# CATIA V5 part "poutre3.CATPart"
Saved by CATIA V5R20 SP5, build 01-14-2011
Part number: poutre3
Bounding box of the stored display mesh (mm): x 0 to 200, y 180.036 to 1475.177, z 210.526 to 649.964
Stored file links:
  F:\iao fini\poutre3.CATPart
  F:\iao fini\iao-finipbgliss.CATProduct
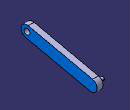
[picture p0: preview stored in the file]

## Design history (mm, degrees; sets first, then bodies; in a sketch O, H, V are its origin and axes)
External parameters (linked from other documents)
  External.rayontrou = 50 mm
  External.epaisseur = 50 mm
Set1
  Plane1 "Plan3": linked copy from another document
  Point1: linked copy from another document
  Point2 "Abis": linked copy from another document
  Point3: linked copy from another document
Body1 (main body)
  Sketch1 on Plane1, origin (100, 0, 0), H (0, 1, 0), V (0, 0, 1)
    circle A1 centre (280, 550) radius 50
    point P1 (280, 550)
    reference projected point E1 (280, 550) from Point2
    circle A2 centre (1375.213, 310.49) radius 25
    point P2 (1375.213, 310.49)
    reference projected point E2 (1375.213, 310.49) from Point3
    arc A3 centre (280, 550) radius 100 from (301.3639, 647.6913) to (258.6361, 452.3087) ccw
    point P3 (280, 550)
    reference projected point E3 (280, 550) from Point2
    arc A4 centre (1375.213, 310.49) radius 100 from (1353.8491, 212.7987) to (1396.5769, 408.1813) ccw
    line L1 (301.3639, 647.6913) -> (1396.5769, 408.1813)
    line L2 (258.6361, 452.3087) -> (1353.8491, 212.7987)
    radius A2 = 25 {= 1/2*External.rayontrou}
    radius A1 = 50 {= External.rayontrou}
    radius A3 = 100 {= External.rayontrou *2}
    radius A4 = 100 {= External.rayontrou *2}
    coincidence: P1 E1, E2 P2, E3 P3
    concentricity: A4 A2
    tangency: L1 A4, L2 A4, L2 A3
    parallelism: L2 L1
  Pad1: profile Sketch1, direction (1, 0, 0), length 100 {= External.epaisseur *2}
  Sketch2 on end face of Pad1, origin (200, 0, 0), H (0, 1, 0), V (0, 0, 1)
    circle A1 centre (1375.213, 310.49) radius 25
    reference projected circle E1 centre (1375.213, 310.49) radius 25 from edge [end face of Pad1 | face of Pad1 from Sketch1.A2]
    radius A1 = 25 {= 1/2*External.rayontrou}
    concentricity: A1 E1
  Pad2: profile Sketch2, direction (-1, 0, 0), length 200 {= 4*External.epaisseur}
